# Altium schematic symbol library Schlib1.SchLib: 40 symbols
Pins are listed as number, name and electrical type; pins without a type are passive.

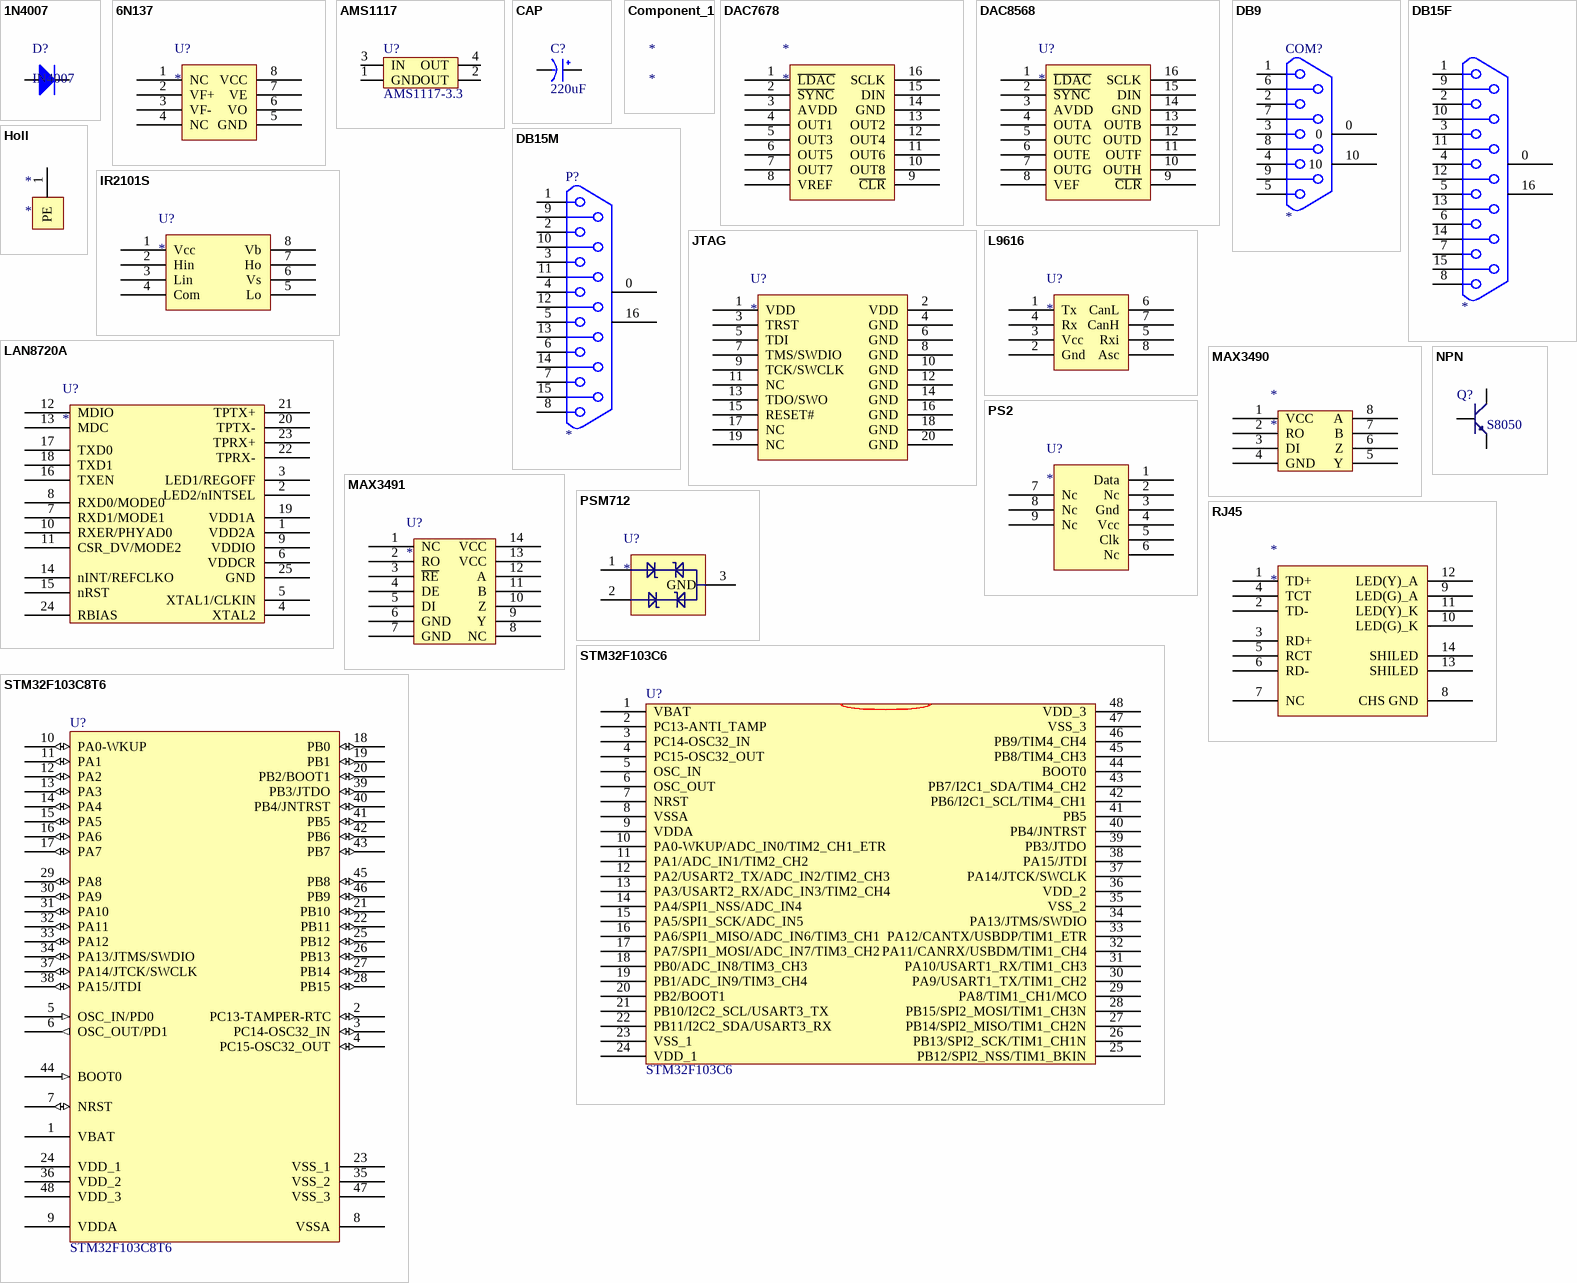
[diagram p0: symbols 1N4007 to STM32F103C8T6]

## 1N4007
designator D?, comment IN4007
footprint DIODE0.4
pins: 1 K, 2 A

## 6N137
designator U?
pins: 1 NC, 2 VF+, 3 VF-, 4 NC, 5 GND, 6 VO, 7 VE, 8 VCC

## AMS1117
designator U?, comment AMS1117-3.3
footprint AMS1117
footprint AMS1117
pins: 1 GND, 2 OUT, 3 IN, 4 OUT

## CAP
designator C?, comment 220uF
footprint C1206
footprint CAP2.54 (RB.1/.2)
footprint CAP5.08 (RB.2/.4)
footprint CAP7.62 (25V 2200uF)
footprint CAP10.16 (50V10000uF)
footprint CAP10.9 (50V 2200uF)
footprint CAP3.0 (100V 10uF)
footprint CAP8.0 (25V/4700uF)
footprint CAP8.0_2 (50V/4700uF)
footprint C7040 (7MM*4MM)
footprint CC1010 (SMD;W:10mm;L:10mm;)
footprint CC6.56.5
footprint CC88 (SMD;W:8mm;L:8mm;)
pins: 1 VCC, 2 GND

## Component_1
designator *

## DAC7678
designator *
pins: 1 ~{LDAC}, 2 ~{SYNC}, 3 AVDD, 4 OUT1, 5 OUT3, 6 OUT5, 7 OUT7, 8 VREF, 9 ~{CLR}, 10 OUT8, 11 OUT6, 12 OUT4, 13 OUT2, 14 GND, 15 DIN, 16 SCLK

## DAC8568
designator U?
pins: 1 ~{LDAC}, 2 ~{SYNC}, 3 AVDD, 4 OUTA, 5 OUTC, 6 OUTE, 7 OUTG, 8 VEF, 9 ~{CLR}, 10 OUTH, 11 OUTF, 12 OUTD, 13 OUTB, 14 GND, 15 DIN, 16 SCLK

## DB9
designator COM?
footprint DB9
footprint DB9-180
footprint DB9-180
pins: 0, 1, 2, 3, 4, 5, 6, 7, 8, 9, 10
2 alternate drawings of the same symbol

## DB15F
designator ?
footprint DB15F
pins: 0, 1, 2, 3, 4, 5, 6, 7, 8, 9, 10, 11, 12, 13, 14, 15, 16
2 alternate drawings of the same symbol

## DB15M
designator P?
footprint DB15M
footprint DB15M
footprint DB15M
pins: 0, 1, 2, 3, 4, 5, 6, 7, 8, 9, 10, 11, 12, 13, 14, 15, 16

## Holl
designator *
pins: 1 PE

## IR2101S
designator U?
footprint SO-8
pins: 1 Vcc, 2 Hin, 3 Lin, 4 Com, 5 Lo, 6 Vs, 7 Ho, 8 Vb

## JTAG
designator U?
pins: 1 VDD, 2 VDD, 3 TRST, 4 GND, 5 TDI, 6 GND, 7 TMS/SWDIO, 8 GND, 9 TCK/SWCLK, 10 GND, 11 NC, 12 GND, 13 TDO/SWO, 14 GND, 15 RESET#, 16 GND, 17 NC, 18 GND, 19 NC, 20 GND

## L9616
designator U?
footprint SOIC8
pins: 1 Tx, 2 Gnd, 3 Vcc, 4 Rx, 5 Rxi, 6 CanL, 7 CanH, 8 Asc

## LAN8720A
designator U?
pins: 1 VDD2A, 2 LED2/nINTSEL, 3 LED1/REGOFF, 4 XTAL2, 5 XTAL1/CLKIN, 6 VDDCR, 7 RXD1/MODE1, 8 RXD0/MODE0, 9 VDDIO, 10 RXER/PHYAD0, 11 CSR_DV/MODE2, 12 MDIO, 13 MDC, 14 nINT/REFCLKO, 15 nRST, 16 TXEN, 17 TXD0, 18 TXD1, 19 VDD1A, 20 TPTX-, 21 TPTX+, 22 TPRX-, 23 TPRX+, 24 RBIAS, 25 GND

## MAX3490
designator *
footprint SOP-4
footprint SO-8
pins: 1 VCC, 2 RO, 3 DI, 4 GND, 5 Y, 6 Z, 7 B, 8 A

## MAX3491
designator U?
footprint MAX3491 (TSOP, 14-Leads, Body 8.65x3.90mm, Pitch 1.27mm, IPC Medium Density)
pins: 1 NC, 2 RO, 3 ~{RE}, 4 DE, 5 DI, 6 GND, 7 GND, 8 NC, 9 Y, 10 Z, 11 B, 12 A, 13 VCC, 14 VCC

## NPN
designator Q?, comment S8050
8050/BCW846/BCW847
footprint SOT-23R
footprint NPN
pins: 1 E, 2 B, 3 C

## PS2
designator U?
footprint PS2
pins: 1 Data, 2 Nc, 3 Gnd, 4 Vcc, 5 Clk, 6 Nc, 7 Nc, 8 Nc, 9 Nc

## PSM712
designator U?
footprint SOT23-3 (SOT23, 3-Leads, Body 2.90x2.45mm, Pitch 0.95mm, IPC Medium Density)
pins: 1, 2, 3 GND

## RJ45
designator *
pins: 1 TD+, 2 TD-, 3 RD+, 4 TCT, 5 RCT, 6 RD-, 7 NC, 8 CHS GND, 9 LED(G)_A, 10 LED(G)_K, 11 LED(Y)_K, 12 LED(Y)_A, 13 SHILED, 14 SHILED

## STM32F103C6
designator U?
footprint LQFP48S (DPIN-0.5)
pins: 1 VBAT, 2 PC13-ANTI_TAMP, 3 PC14-OSC32_IN, 4 PC15-OSC32_OUT, 5 OSC_IN, 6 OSC_OUT, 7 NRST, 8 VSSA, 9 VDDA, 10 PA0-WKUP/ADC_IN0/TIM2_CH1_ETR, 11 PA1/ADC_IN1/TIM2_CH2, 12 PA2/USART2_TX/ADC_IN2/TIM2_CH3, 13 PA3/USART2_RX/ADC_IN3/TIM2_CH4, 14 PA4/SPI1_NSS/ADC_IN4, 15 PA5/SPI1_SCK/ADC_IN5, 16 PA6/SPI1_MISO/ADC_IN6/TIM3_CH1, 17 PA7/SPI1_MOSI/ADC_IN7/TIM3_CH2, 18 PB0/ADC_IN8/TIM3_CH3, 19 PB1/ADC_IN9/TIM3_CH4, 20 PB2/BOOT1, 21 PB10/I2C2_SCL/USART3_TX, 22 PB11/I2C2_SDA/USART3_RX, 23 VSS_1, 24 VDD_1, 25 PB12/SPI2_NSS/TIM1_BKIN, 26 PB13/SPI2_SCK/TIM1_CH1N, 27 PB14/SPI2_MISO/TIM1_CH2N, 28 PB15/SPI2_MOSI/TIM1_CH3N, 29 PA8/TIM1_CH1/MCO, 30 PA9/USART1_TX/TIM1_CH2, 31 PA10/USART1_RX/TIM1_CH3, 32 PA11/CANRX/USBDM/TIM1_CH4, 33 PA12/CANTX/USBDP/TIM1_ETR, 34 PA13/JTMS/SWDIO, 35 VSS_2, 36 VDD_2, 37 PA14/JTCK/SWCLK, 38 PA15/JTDI, 39 PB3/JTDO, 40 PB4/JNTRST, 41 PB5, 42 PB6/I2C1_SCL/TIM4_CH1, 43 PB7/I2C1_SDA/TIM4_CH2, 44 BOOT0, 45 PB8/TIM4_CH3, 46 PB9/TIM4_CH4, 47 VSS_3, 48 VDD_3
2 alternate drawings of the same symbol

## STM32F103C8T6
designator U?
footprint LQFP-48
pins: 1 VBAT (power), 2 PC13-TAMPER-RTC (io), 3 PC14-OSC32_IN (io), 4 PC15-OSC32_OUT (io), 5 OSC_IN/PD0 (in), 6 OSC_OUT/PD1 (out), 7 NRST (io), 8 VSSA (power), 9 VDDA (power), 10 PA0-WKUP (io), 11 PA1 (io), 12 PA2 (io), 13 PA3 (io), 14 PA4 (io), 15 PA5 (io), 16 PA6 (io), 17 PA7 (io), 18 PB0 (io), 19 PB1 (io), 20 PB2/BOOT1 (io), 21 PB10 (io), 22 PB11 (io), 23 VSS_1 (power), 24 VDD_1 (power), 25 PB12 (io), 26 PB13 (io), 27 PB14 (io), 28 PB15 (io), 29 PA8 (io), 30 PA9 (io), 31 PA10 (io), 32 PA11 (io), 33 PA12 (io), 34 PA13/JTMS/SWDIO (io), 35 VSS_2 (power), 36 VDD_2 (power), 37 PA14/JTCK/SWCLK (io), 38 PA15/JTDI (io), 39 PB3/JTDO (io), 40 PB4/JNTRST (io), 41 PB5 (io), 42 PB6 (io), 43 PB7 (io), 44 BOOT0 (in), 45 PB8 (io), 46 PB9 (io), 47 VSS_3 (power), 48 VDD_3 (power)

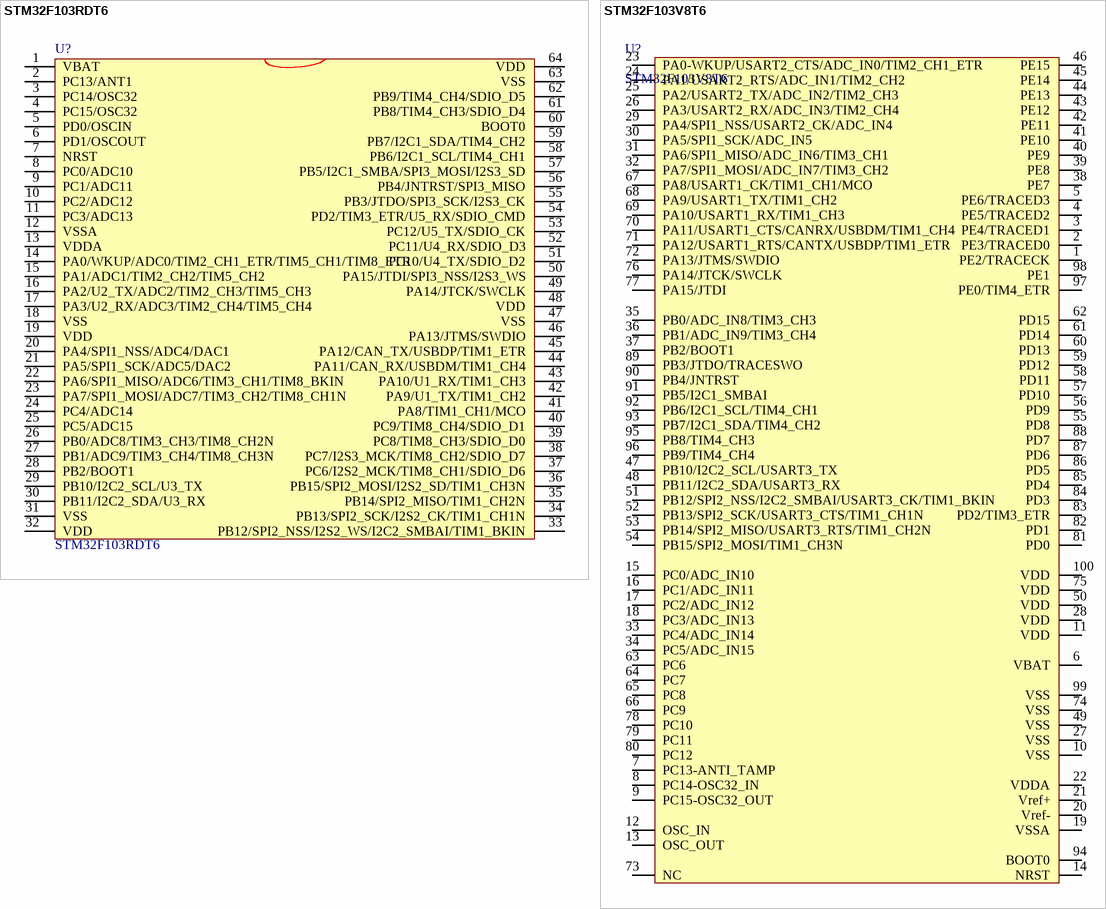
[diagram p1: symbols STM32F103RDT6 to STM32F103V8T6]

## STM32F103RDT6
designator U?
footprint LQFP64
footprint VRCNC_LQFP64
pins: 1 VBAT, 2 PC13/ANT1, 3 PC14/OSC32, 4 PC15/OSC32, 5 PD0/OSCIN, 6 PD1/OSCOUT, 7 NRST, 8 PC0/ADC10, 9 PC1/ADC11, 10 PC2/ADC12, 11 PC3/ADC13, 12 VSSA, 13 VDDA, 14 PA0/WKUP/ADC0/TIM2_CH1_ETR/TIM5_CH1/TIM8_ETR, 15 PA1/ADC1/TIM2_CH2/TIM5_CH2, 16 PA2/U2_TX/ADC2/TIM2_CH3/TIM5_CH3, 17 PA3/U2_RX/ADC3/TIM2_CH4/TIM5_CH4, 18 VSS, 19 VDD, 20 PA4/SPI1_NSS/ADC4/DAC1, 21 PA5/SPI1_SCK/ADC5/DAC2, 22 PA6/SPI1_MISO/ADC6/TIM3_CH1/TIM8_BKIN, 23 PA7/SPI1_MOSI/ADC7/TIM3_CH2/TIM8_CH1N, 24 PC4/ADC14, 25 PC5/ADC15, 26 PB0/ADC8/TIM3_CH3/TIM8_CH2N, 27 PB1/ADC9/TIM3_CH4/TIM8_CH3N, 28 PB2/BOOT1, 29 PB10/I2C2_SCL/U3_TX, 30 PB11/I2C2_SDA/U3_RX, 31 VSS, 32 VDD, 33 PB12/SPI2_NSS/I2S2_WS/I2C2_SMBAI/TIM1_BKIN, 34 PB13/SPI2_SCK/I2S2_CK/TIM1_CH1N, 35 PB14/SPI2_MISO/TIM1_CH2N, 36 PB15/SPI2_MOSI/I2S2_SD/TIM1_CH3N, 37 PC6/I2S2_MCK/TIM8_CH1/SDIO_D6, 38 PC7/I2S3_MCK/TIM8_CH2/SDIO_D7, 39 PC8/TIM8_CH3/SDIO_D0, 40 PC9/TIM8_CH4/SDIO_D1, 41 PA8/TIM1_CH1/MCO, 42 PA9/U1_TX/TIM1_CH2, 43 PA10/U1_RX/TIM1_CH3, 44 PA11/CAN_RX/USBDM/TIM1_CH4, 45 PA12/CAN_TX/USBDP/TIM1_ETR, 46 PA13/JTMS/SWDIO, 47 VSS, 48 VDD, 49 PA14/JTCK/SWCLK, 50 PA15/JTDI/SPI3_NSS/I2S3_WS, 51 PC10/U4_TX/SDIO_D2, 52 PC11/U4_RX/SDIO_D3, 53 PC12/U5_TX/SDIO_CK, 54 PD2/TIM3_ETR/U5_RX/SDIO_CMD, 55 PB3/JTDO/SPI3_SCK/I2S3_CK, 56 PB4/JNTRST/SPI3_MISO, 57 PB5/I2C1_SMBA/SPI3_MOSI/I2S3_SD, 58 PB6/I2C1_SCL/TIM4_CH1, 59 PB7/I2C1_SDA/TIM4_CH2, 60 BOOT0, 61 PB8/TIM4_CH3/SDIO_D4, 62 PB9/TIM4_CH4/SDIO_D5, 63 VSS, 64 VDD

## STM32F103V8T6
designator U?
footprint LQFP100 (TSQFP, 100-Leads, Body 16.0x16.0mm (max), Pitch 0.50mm, IPC Medium Density)
pins: 1 PE2/TRACECK, 2 PE3/TRACED0, 3 PE4/TRACED1, 4 PE5/TRACED2, 5 PE6/TRACED3, 6 VBAT, 7 PC13-ANTI_TAMP, 8 PC14-OSC32_IN, 9 PC15-OSC32_OUT, 10 VSS, 11 VDD, 12 OSC_IN, 13 OSC_OUT, 14 NRST, 15 PC0/ADC_IN10, 16 PC1/ADC_IN11, 17 PC2/ADC_IN12, 18 PC3/ADC_IN13, 19 VSSA, 20 Vref-, 21 Vref+, 22 VDDA, 23 PA0-WKUP/USART2_CTS/ADC_IN0/TIM2_CH1_ETR, 24 PA1/USART2_RTS/ADC_IN1/TIM2_CH2, 25 PA2/USART2_TX/ADC_IN2/TIM2_CH3, 26 PA3/USART2_RX/ADC_IN3/TIM2_CH4, 27 VSS, 28 VDD, 29 PA4/SPI1_NSS/USART2_CK/ADC_IN4, 30 PA5/SPI1_SCK/ADC_IN5, 31 PA6/SPI1_MISO/ADC_IN6/TIM3_CH1, 32 PA7/SPI1_MOSI/ADC_IN7/TIM3_CH2, 33 PC4/ADC_IN14, 34 PC5/ADC_IN15, 35 PB0/ADC_IN8/TIM3_CH3, 36 PB1/ADC_IN9/TIM3_CH4, 37 PB2/BOOT1, 38 PE7, 39 PE8, 40 PE9, 41 PE10, 42 PE11, 43 PE12, 44 PE13, 45 PE14, 46 PE15, 47 PB10/I2C2_SCL/USART3_TX, 48 PB11/I2C2_SDA/USART3_RX, 49 VSS, 50 VDD, 51 PB12/SPI2_NSS/I2C2_SMBAI/USART3_CK/TIM1_BKIN, 52 PB13/SPI2_SCK/USART3_CTS/TIM1_CH1N, 53 PB14/SPI2_MISO/USART3_RTS/TIM1_CH2N, 54 PB15/SPI2_MOSI/TIM1_CH3N, 55 PD8, 56 PD9, 57 PD10, 58 PD11, 59 PD12, 60 PD13, 61 PD14, 62 PD15, 63 PC6, 64 PC7, 65 PC8, 66 PC9, 67 PA8/USART1_CK/TIM1_CH1/MCO, 68 PA9/USART1_TX/TIM1_CH2, 69 PA10/USART1_RX/TIM1_CH3, 70 PA11/USART1_CTS/CANRX/USBDM/TIM1_CH4, 71 PA12/USART1_RTS/CANTX/USBDP/TIM1_ETR, 72 PA13/JTMS/SWDIO, 73 NC, 74 VSS, 75 VDD, 76 PA14/JTCK/SWCLK, 77 PA15/JTDI, 78 PC10, 79 PC11, 80 PC12, 81 PD0, 82 PD1, 83 PD2/TIM3_ETR, 84 PD3, 85 PD4, 86 PD5, 87 PD6, 88 PD7, 89 PB3/JTDO/TRACESWO, 90 PB4/JNTRST, 91 PB5/I2C1_SMBAI, 92 PB6/I2C1_SCL/TIM4_CH1, 93 PB7/I2C1_SDA/TIM4_CH2, 94 BOOT0, 95 PB8/TIM4_CH3, 96 PB9/TIM4_CH4, 97 PE0/TIM4_ETR, 98 PE1, 99 VSS, 100 VDD

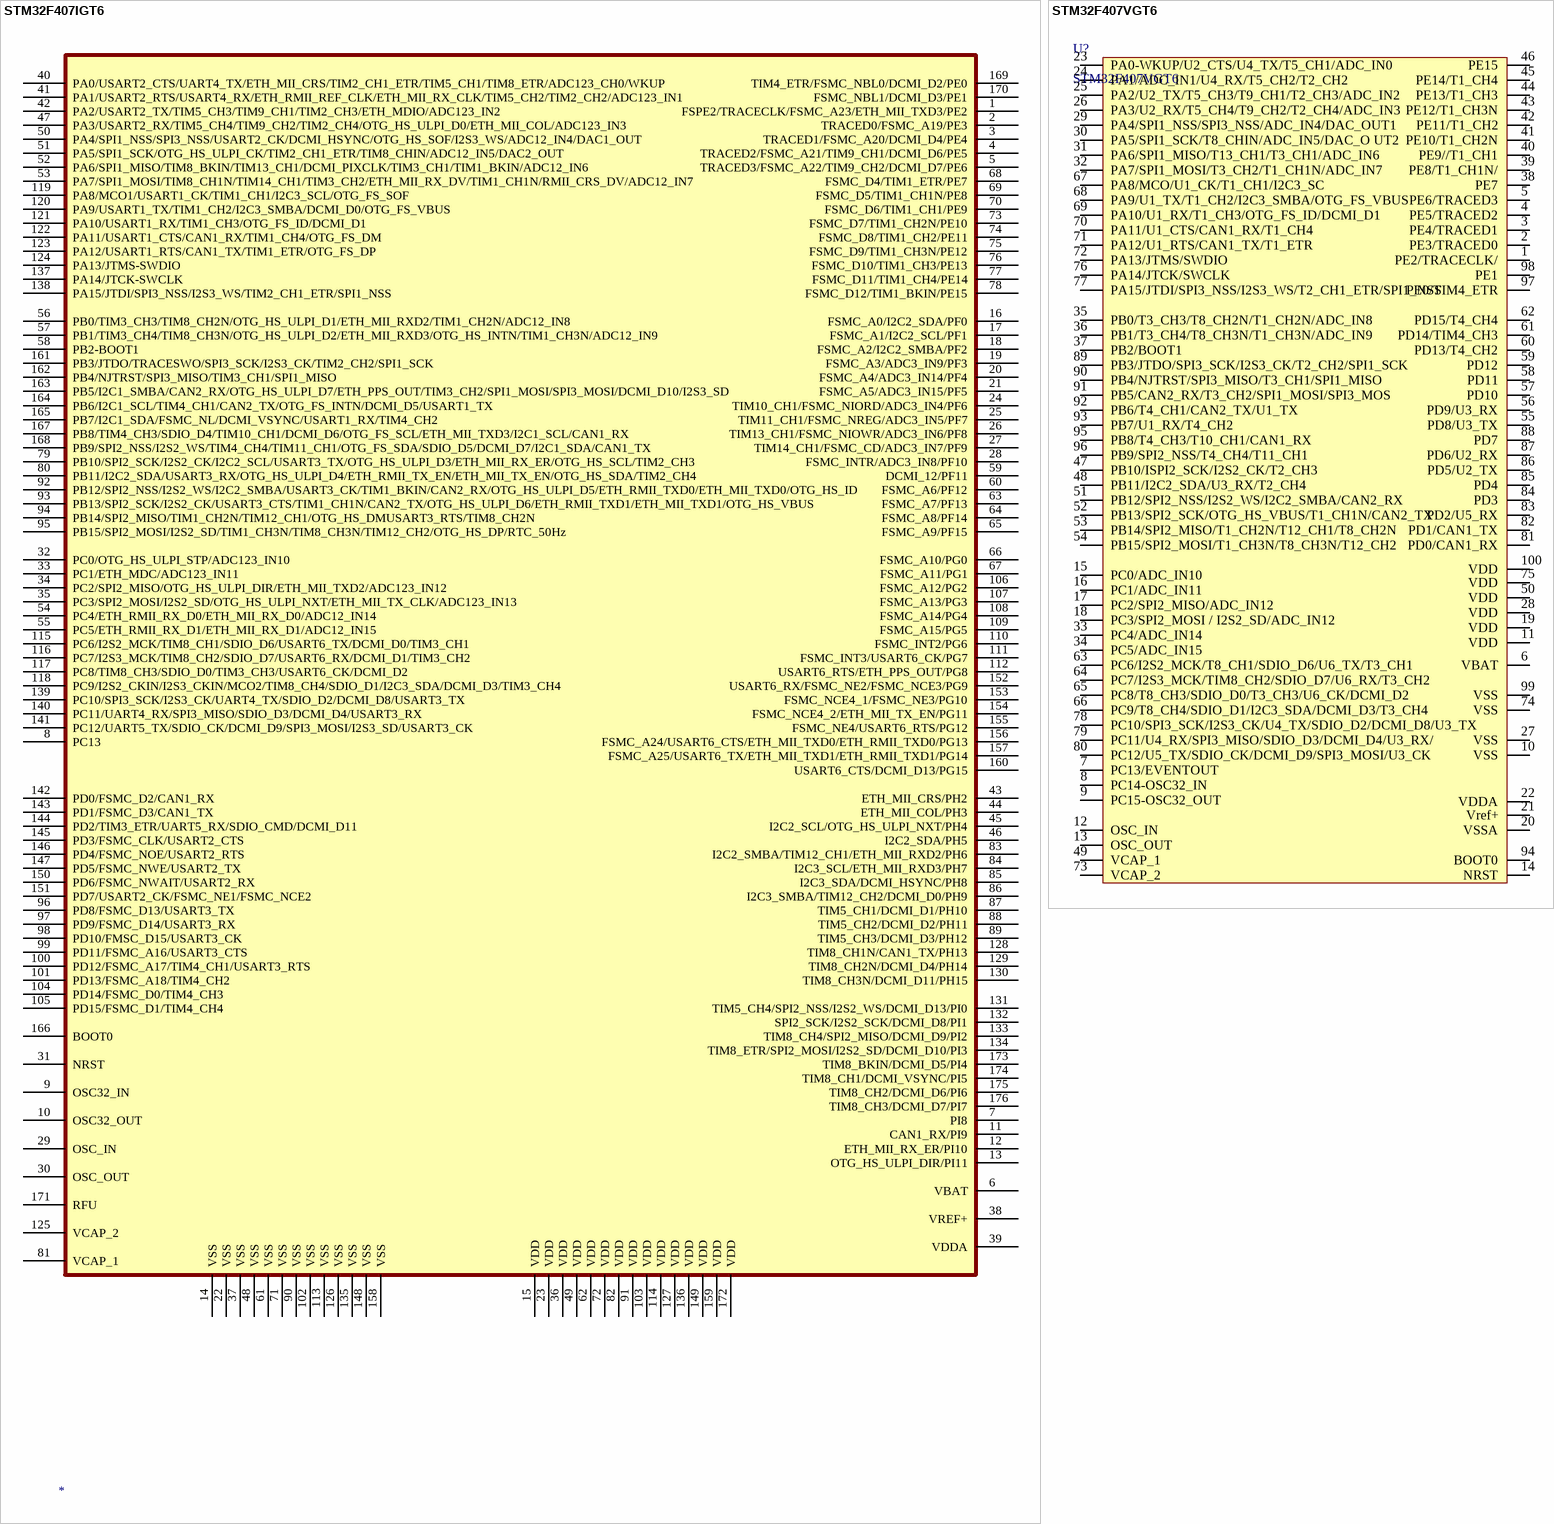
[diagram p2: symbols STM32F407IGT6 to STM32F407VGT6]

## STM32F407IGT6
designator ?
pins: 1 FSPE2/TRACECLK/FSMC_A23/ETH_MII_TXD3/PE2, 2 TRACED0/FSMC_A19/PE3, 3 TRACED1/FSMC_A20/DCMI_D4/PE4, 4 TRACED2/FSMC_A21/TIM9_CH1/DCMI_D6/PE5, 5 TRACED3/FSMC_A22/TIM9_CH2/DCMI_D7/PE6, 6 VBAT, 7 PI8, 8 PC13, 9 OSC32_IN, 10 OSC32_OUT, 11 CAN1_RX/PI9, 12 ETH_MII_RX_ER/PI10, 13 OTG_HS_ULPI_DIR/PI11, 14 VSS, 15 VDD, 16 FSMC_A0/I2C2_SDA/PF0, 17 FSMC_A1/I2C2_SCL/PF1, 18 FSMC_A2/I2C2_SMBA/PF2, 19 FSMC_A3/ADC3_IN9/PF3, 20 FSMC_A4/ADC3_IN14/PF4, 21 FSMC_A5/ADC3_IN15/PF5, 22 VSS, 23 VDD, 24 TIM10_CH1/FSMC_NIORD/ADC3_IN4/PF6, 25 TIM11_CH1/FSMC_NREG/ADC3_IN5/PF7, 26 TIM13_CH1/FSMC_NIOWR/ADC3_IN6/PF8, 27 TIM14_CH1/FSMC_CD/ADC3_IN7/PF9, 28 FSMC_INTR/ADC3_IN8/PF10, 29 OSC_IN, 30 OSC_OUT, 31 NRST, 32 PC0/OTG_HS_ULPI_STP/ADC123_IN10, 33 PC1/ETH_MDC/ADC123_IN11, 34 PC2/SPI2_MISO/OTG_HS_ULPI_DIR/ETH_MII_TXD2/ADC123_IN12, 35 PC3/SPI2_MOSI/I2S2_SD/OTG_HS_ULPI_NXT/ETH_MII_TX_CLK/ADC123_IN13, 36 VDD, 37 VSS, 38 VREF+, 39 VDDA, 40 PA0/USART2_CTS/UART4_TX/ETH_MII_CRS/TIM2_CH1_ETR/TIM5_CH1/TIM8_ETR/ADC123_CH0/WKUP, 41 PA1/USART2_RTS/USART4_RX/ETH_RMII_REF_CLK/ETH_MII_RX_CLK/TIM5_CH2/TIM2_CH2/ADC123_IN1, 42 PA2/USART2_TX/TIM5_CH3/TIM9_CH1/TIM2_CH3/ETH_MDIO/ADC123_IN2, 43 ETH_MII_CRS/PH2, 44 ETH_MII_COL/PH3, 45 I2C2_SCL/OTG_HS_ULPI_NXT/PH4, 46 I2C2_SDA/PH5, 47 PA3/USART2_RX/TIM5_CH4/TIM9_CH2/TIM2_CH4/OTG_HS_ULPI_D0/ETH_MII_COL/ADC123_IN3, 48 VSS, 49 VDD, 50 PA4/SPI1_NSS/SPI3_NSS/USART2_CK/DCMI_HSYNC/OTG_HS_SOF/I2S3_WS/ADC12_IN4/DAC1_OUT, 51 PA5/SPI1_SCK/OTG_HS_ULPI_CK/TIM2_CH1_ETR/TIM8_CHIN/ADC12_IN5/DAC2_OUT, 52 PA6/SPI1_MISO/TIM8_BKIN/TIM13_CH1/DCMI_PIXCLK/TIM3_CH1/TIM1_BKIN/ADC12_IN6, 53 PA7/SPI1_MOSI/TIM8_CH1N/TIM14_CH1/TIM3_CH2/ETH_MII_RX_DV/TIM1_CH1N/RMII_CRS_DV/ADC12_IN7, 54 PC4/ETH_RMII_RX_D0/ETH_MII_RX_D0/ADC12_IN14, 55 PC5/ETH_RMII_RX_D1/ETH_MII_RX_D1/ADC12_IN15, 56 PB0/TIM3_CH3/TIM8_CH2N/OTG_HS_ULPI_D1/ETH_MII_RXD2/TIM1_CH2N/ADC12_IN8, 57 PB1/TIM3_CH4/TIM8_CH3N/OTG_HS_ULPI_D2/ETH_MII_RXD3/OTG_HS_INTN/TIM1_CH3N/ADC12_IN9, 58 PB2-BOOT1, 59 DCMI_12/PF11, 60 FSMC_A6/PF12, 61 VSS, 62 VDD, 63 FSMC_A7/PF13, 64 FSMC_A8/PF14, 65 FSMC_A9/PF15, 66 FSMC_A10/PG0, 67 FSMC_A11/PG1, 68 FSMC_D4/TIM1_ETR/PE7, 69 FSMC_D5/TIM1_CH1N/PE8, 70 FSMC_D6/TIM1_CH1/PE9, 71 VSS, 72 VDD, 73 FSMC_D7/TIM1_CH2N/PE10, 74 FSMC_D8/TIM1_CH2/PE11, 75 FSMC_D9/TIM1_CH3N/PE12, 76 FSMC_D10/TIM1_CH3/PE13, 77 FSMC_D11/TIM1_CH4/PE14, 78 FSMC_D12/TIM1_BKIN/PE15, 79 PB10/SPI2_SCK/I2S2_CK/I2C2_SCL/USART3_TX/OTG_HS_ULPI_D3/ETH_MII_RX_ER/OTG_HS_SCL/TIM2_CH3, 80 PB11/I2C2_SDA/USART3_RX/OTG_HS_ULPI_D4/ETH_RMII_TX_EN/ETH_MII_TX_EN/OTG_HS_SDA/TIM2_CH4, 81 VCAP_1, 82 VDD, 83 I2C2_SMBA/TIM12_CH1/ETH_MII_RXD2/PH6, 84 I2C3_SCL/ETH_MII_RXD3/PH7, 85 I2C3_SDA/DCMI_HSYNC/PH8, 86 I2C3_SMBA/TIM12_CH2/DCMI_D0/PH9, 87 TIM5_CH1/DCMI_D1/PH10, 88 TIM5_CH2/DCMI_D2/PH11, 89 TIM5_CH3/DCMI_D3/PH12, 90 VSS, 91 VDD, 92 PB12/SPI2_NSS/I2S2_WS/I2C2_SMBA/USART3_CK/TIM1_BKIN/CAN2_RX/OTG_HS_ULPI_D5/ETH_RMII_TXD0/ETH_MII_TXD0/OTG_HS_ID, 93 PB13/SPI2_SCK/I2S2_CK/USART3_CTS/TIM1_CH1N/CAN2_TX/OTG_HS_ULPI_D6/ETH_RMII_TXD1/ETH_MII_TXD1/OTG_HS_VBUS, 94 PB14/SPI2_MISO/TIM1_CH2N/TIM12_CH1/OTG_HS_DMUSART3_RTS/TIM8_CH2N, 95 PB15/SPI2_MOSI/I2S2_SD/TIM1_CH3N/TIM8_CH3N/TIM12_CH2/OTG_HS_DP/RTC_50Hz, 96 PD8/FSMC_D13/USART3_TX, 97 PD9/FSMC_D14/USART3_RX, 98 PD10/FMSC_D15/USART3_CK, 99 PD11/FSMC_A16/USART3_CTS, 100 PD12/FSMC_A17/TIM4_CH1/USART3_RTS, 101 PD13/FSMC_A18/TIM4_CH2, 102 VSS, 103 VDD, 104 PD14/FSMC_D0/TIM4_CH3, 105 PD15/FSMC_D1/TIM4_CH4, 106 FSMC_A12/PG2, 107 FSMC_A13/PG3, 108 FSMC_A14/PG4, 109 FSMC_A15/PG5, 110 FSMC_INT2/PG6, 111 FSMC_INT3/USART6_CK/PG7, 112 USART6_RTS/ETH_PPS_OUT/PG8, 113 VSS, 114 VDD, 115 PC6/I2S2_MCK/TIM8_CH1/SDIO_D6/USART6_TX/DCMI_D0/TIM3_CH1, 116 PC7/I2S3_MCK/TIM8_CH2/SDIO_D7/USART6_RX/DCMI_D1/TIM3_CH2, 117 PC8/TIM8_CH3/SDIO_D0/TIM3_CH3/USART6_CK/DCMI_D2, 118 PC9/I2S2_CKIN/I2S3_CKIN/MCO2/TIM8_CH4/SDIO_D1/I2C3_SDA/DCMI_D3/TIM3_CH4, 119 PA8/MCO1/USART1_CK/TIM1_CH1/I2C3_SCL/OTG_FS_SOF, 120 PA9/USART1_TX/TIM1_CH2/I2C3_SMBA/DCMI_D0/OTG_FS_VBUS, 121 PA10/USART1_RX/TIM1_CH3/OTG_FS_ID/DCMI_D1, 122 PA11/USART1_CTS/CAN1_RX/TIM1_CH4/OTG_FS_DM, 123 PA12/USART1_RTS/CAN1_TX/TIM1_ETR/OTG_FS_DP, 124 PA13/JTMS-SWDIO, 125 VCAP_2, 126 VSS, 127 VDD, 128 TIM8_CH1N/CAN1_TX/PH13, 129 TIM8_CH2N/DCMI_D4/PH14, 130 TIM8_CH3N/DCMI_D11/PH15, 131 TIM5_CH4/SPI2_NSS/I2S2_WS/DCMI_D13/PI0, 132 SPI2_SCK/I2S2_SCK/DCMI_D8/PI1, 133 TIM8_CH4/SPI2_MISO/DCMI_D9/PI2, 134 TIM8_ETR/SPI2_MOSI/I2S2_SD/DCMI_D10/PI3, 135 VSS, 136 VDD, 137 PA14/JTCK-SWCLK, 138 PA15/JTDI/SPI3_NSS/I2S3_WS/TIM2_CH1_ETR/SPI1_NSS, 139 PC10/SPI3_SCK/I2S3_CK/UART4_TX/SDIO_D2/DCMI_D8/USART3_TX, 140 PC11/UART4_RX/SPI3_MISO/SDIO_D3/DCMI_D4/USART3_RX, 141 PC12/UART5_TX/SDIO_CK/DCMI_D9/SPI3_MOSI/I2S3_SD/USART3_CK, 142 PD0/FSMC_D2/CAN1_RX, 143 PD1/FSMC_D3/CAN1_TX, 144 PD2/TIM3_ETR/UART5_RX/SDIO_CMD/DCMI_D11, 145 PD3/FSMC_CLK/USART2_CTS, 146 PD4/FSMC_NOE/USART2_RTS, 147 PD5/FSMC_NWE/USART2_TX, 148 VSS, 149 VDD, 150 PD6/FSMC_NWAIT/USART2_RX, 151 PD7/USART2_CK/FSMC_NE1/FSMC_NCE2, 152 USART6_RX/FSMC_NE2/FSMC_NCE3/PG9, 153 FSMC_NCE4_1/FSMC_NE3/PG10, 154 FSMC_NCE4_2/ETH_MII_TX_EN/PG11, 155 FSMC_NE4/USART6_RTS/PG12, 156 FSMC_A24/USART6_CTS/ETH_MII_TXD0/ETH_RMII_TXD0/PG13, 157 FSMC_A25/USART6_TX/ETH_MII_TXD1/ETH_RMII_TXD1/PG14, 158 VSS, 159 VDD, 160 USART6_CTS/DCMI_D13/PG15, 161 PB3/JTDO/TRACESWO/SPI3_SCK/I2S3_CK/TIM2_CH2/SPI1_SCK, 162 PB4/NJTRST/SPI3_MISO/TIM3_CH1/SPI1_MISO, 163 PB5/I2C1_SMBA/CAN2_RX/OTG_HS_ULPI_D7/ETH_PPS_OUT/TIM3_CH2/SPI1_MOSI/SPI3_MOSI/DCMI_D10/I2S3_SD, 164 PB6/I2C1_SCL/TIM4_CH1/CAN2_TX/OTG_FS_INTN/DCMI_D5/USART1_TX, 165 PB7/I2C1_SDA/FSMC_NL/DCMI_VSYNC/USART1_RX/TIM4_CH2, 166 BOOT0, 167 PB8/TIM4_CH3/SDIO_D4/TIM10_CH1/DCMI_D6/OTG_FS_SCL/ETH_MII_TXD3/I2C1_SCL/CAN1_RX, 168 PB9/SPI2_NSS/I2S2_WS/TIM4_CH4/TIM11_CH1/OTG_FS_SDA/SDIO_D5/DCMI_D7/I2C1_SDA/CAN1_TX, 169 TIM4_ETR/FSMC_NBL0/DCMI_D2/PE0, 170 FSMC_NBL1/DCMI_D3/PE1, 171 RFU, 172 VDD, 173 TIM8_BKIN/DCMI_D5/PI4, 174 TIM8_CH1/DCMI_VSYNC/PI5, 175 TIM8_CH2/DCMI_D6/PI6, 176 TIM8_CH3/DCMI_D7/PI7

## STM32F407VGT6
designator U?
footprint LQFP100 (TSQFP, 100-Leads, Body 16.0x16.0mm (max), Pitch 0.50mm, IPC Medium Density)
pins: 1 PE2/TRACECLK/, 2 PE3/TRACED0, 3 PE4/TRACED1, 4 PE5/TRACED2, 5 PE6/TRACED3, 6 VBAT, 7 PC13/EVENTOUT, 8 PC14-OSC32_IN, 9 PC15-OSC32_OUT, 10 VSS, 11 VDD, 12 OSC_IN, 13 OSC_OUT, 14 NRST, 15 PC0/ADC_IN10, 16 PC1/ADC_IN11, 17 PC2/SPI2_MISO/ADC_IN12, 18 PC3/SPI2_MOSI / I2S2_SD/ADC_IN12 , 19 VDD, 20 VSSA, 21 Vref+, 22 VDDA, 23 PA0-WKUP/U2_CTS/U4_TX/T5_CH1/ADC_IN0, 24 PA1/ADC_IN1/U4_RX/T5_CH2/T2_CH2, 25 PA2/U2_TX/T5_CH3/T9_CH1/T2_CH3/ADC_IN2, 26 PA3/U2_RX/T5_CH4/T9_CH2/T2_CH4/ADC_IN3, 27 VSS, 28 VDD, 29 PA4/SPI1_NSS/SPI3_NSS/ADC_IN4/DAC_OUT1, 30 PA5/SPI1_SCK/T8_CHIN/ADC_IN5/DAC_O UT2, 31 PA6/SPI1_MISO/T13_CH1/T3_CH1/ADC_IN6, 32 PA7/SPI1_MOSI/T3_CH2/T1_CH1N/ADC_IN7, 33 PC4/ADC_IN14, 34 PC5/ADC_IN15, 35 PB0/T3_CH3/T8_CH2N/T1_CH2N/ADC_IN8, 36 PB1/T3_CH4/T8_CH3N/T1_CH3N/ADC_IN9, 37 PB2/BOOT1, 38 PE7, 39 PE8/T1_CH1N/, 40 PE9//T1_CH1, 41 PE10/T1_CH2N, 42 PE11/T1_CH2, 43 PE12/T1_CH3N, 44 PE13/T1_CH3, 45 PE14/T1_CH4, 46 PE15, 47 PB10/ISPI2_SCK/I2S2_CK/T2_CH3, 48 PB11/I2C2_SDA/U3_RX/T2_CH4, 49 VCAP_1, 50 VDD, 51 PB12/SPI2_NSS/I2S2_WS/I2C2_SMBA/CAN2_RX, 52 PB13/SPI2_SCK/OTG_HS_VBUS/T1_CH1N/CAN2_TX, 53 PB14/SPI2_MISO/T1_CH2N/T12_CH1/T8_CH2N, 54 PB15/SPI2_MOSI/T1_CH3N/T8_CH3N/T12_CH2, 55 PD8/U3_TX, 56 PD9/U3_RX, 57 PD10, 58 PD11, 59 PD12, 60 PD13/T4_CH2, 61 PD14/TIM4_CH3, 62 PD15/T4_CH4, 63 PC6/I2S2_MCK/T8_CH1/SDIO_D6/U6_TX/T3_CH1, 64 PC7/I2S3_MCK/TIM8_CH2/SDIO_D7/U6_RX/T3_CH2, 65 PC8/T8_CH3/SDIO_D0/T3_CH3/U6_CK/DCMI_D2, 66 PC9/T8_CH4/SDIO_D1/I2C3_SDA/DCMI_D3/T3_CH4, 67 PA8/MCO/U1_CK/T1_CH1/I2C3_SC, 68 PA9/U1_TX/T1_CH2/I2C3_SMBA/OTG_FS_VBUS, 69 PA10/U1_RX/T1_CH3/OTG_FS_ID/DCMI_D1, 70 PA11/U1_CTS/CAN1_RX/T1_CH4, 71 PA12/U1_RTS/CAN1_TX/T1_ETR, 72 PA13/JTMS/SWDIO, 73 VCAP_2, 74 VSS, 75 VDD, 76 PA14/JTCK/SWCLK, 77 PA15/JTDI/SPI3_NSS/I2S3_WS/T2_CH1_ETR/SPI1_NSS, 78 PC10/SPI3_SCK/I2S3_CK/U4_TX/SDIO_D2/DCMI_D8/U3_TX, 79 PC11/U4_RX/SPI3_MISO/SDIO_D3/DCMI_D4/U3_RX/, 80 PC12/U5_TX/SDIO_CK/DCMI_D9/SPI3_MOSI/U3_CK, 81 PD0/CAN1_RX, 82 PD1/CAN1_TX, 83 PD2/U5_RX, 84 PD3, 85 PD4, 86 PD5/U2_TX, 87 PD6/U2_RX, 88 PD7, 89 PB3/JTDO/SPI3_SCK/I2S3_CK/T2_CH2/SPI1_SCK, 90 PB4/NJTRST/SPI3_MISO/T3_CH1/SPI1_MISO, 91 PB5/CAN2_RX/T3_CH2/SPI1_MOSI/SPI3_MOS, 92 PB6/T4_CH1/CAN2_TX/U1_TX, 93 PB7/U1_RX/T4_CH2, 94 BOOT0, 95 PB8/T4_CH3/T10_CH1/CAN1_RX, 96 PB9/SPI2_NSS/T4_CH4/T11_CH1, 97 PE0/TIM4_ETR, 98 PE1, 99 VSS, 100 VDD

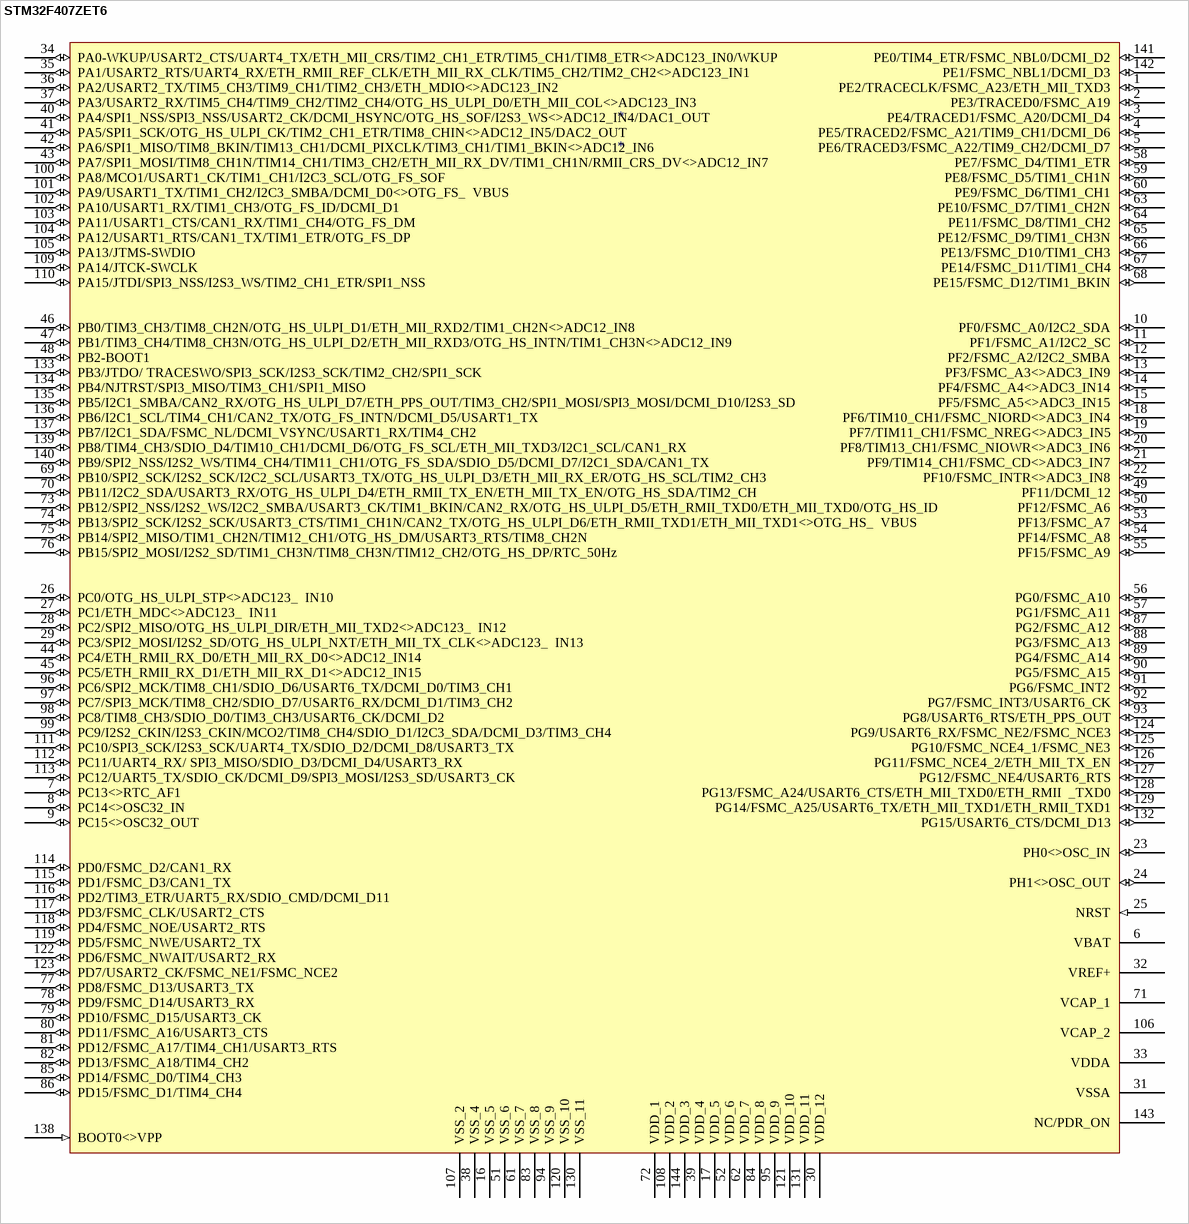
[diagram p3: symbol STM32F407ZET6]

## STM32F407ZET6
designator *
pins: 1 PE2/TRACECLK/FSMC_A23/ETH_MII_TXD3 (io), 2 PE3/TRACED0/FSMC_A19 (io), 3 PE4/TRACED1/FSMC_A20/DCMI_D4 (io), 4 PE5/TRACED2/FSMC_A21/TIM9_CH1/DCMI_D6 (io), 5 PE6/TRACED3/FSMC_A22/TIM9_CH2/DCMI_D7 (io), 6 VBAT (power), 7 PC13<>RTC_AF1 (io), 8 PC14<>OSC32_IN (io), 9 PC15<>OSC32_OUT (io), 10 PF0/FSMC_A0/I2C2_SDA (io), 11 PF1/FSMC_A1/I2C2_SC (io), 12 PF2/FSMC_A2/I2C2_SMBA (io), 13 PF3/FSMC_A3<>ADC3_IN9 (io), 14 PF4/FSMC_A4<>ADC3_IN14 (io), 15 PF5/FSMC_A5<>ADC3_IN15 (io), 16 VSS_5 (power), 17 VDD_5 (power), 18 PF6/TIM10_CH1/FSMC_NIORD<>ADC3_IN4 (io), 19 PF7/TIM11_CH1/FSMC_NREG<>ADC3_IN5 (io), 20 PF8/TIM13_CH1/FSMC_NIOWR<>ADC3_IN6 (io), 21 PF9/TIM14_CH1/FSMC_CD<>ADC3_IN7 (io), 22 PF10/FSMC_INTR<>ADC3_IN8 (io), 23 PH0<>OSC_IN (io), 24 PH1<>OSC_OUT (io), 25 NRST (in), 26 PC0/OTG_HS_ULPI_STP<>ADC123_  IN10 (io), 27 PC1/ETH_MDC<>ADC123_  IN11 (io), 28 PC2/SPI2_MISO/OTG_HS_ULPI_DIR/ETH_MII_TXD2<>ADC123_  IN12 (io), 29 PC3/SPI2_MOSI/I2S2_SD/OTG_HS_ULPI_NXT/ETH_MII_TX_CLK<>ADC123_  IN13 (io), 30 VDD_12 (power), 31 VSSA (power), 32 VREF+ (power), 33 VDDA (power), 34 PA0-WKUP/USART2_CTS/UART4_TX/ETH_MII_CRS/TIM2_CH1_ETR/TIM5_CH1/TIM8_ETR<>ADC123_IN0/WKUP (io), 35 PA1/USART2_RTS/UART4_RX/ETH_RMII_REF_CLK/ETH_MII_RX_CLK/TIM5_CH2/TIM2_CH2<>ADC123_IN1 (io), 36 PA2/USART2_TX/TIM5_CH3/TIM9_CH1/TIM2_CH3/ETH_MDIO<>ADC123_IN2 (io), 37 PA3/USART2_RX/TIM5_CH4/TIM9_CH2/TIM2_CH4/OTG_HS_ULPI_D0/ETH_MII_COL<>ADC123_IN3 (io), 38 VSS_4 (power), 39 VDD_4 (power), 40 PA4/SPI1_NSS/SPI3_NSS/USART2_CK/DCMI_HSYNC/OTG_HS_SOF/I2S3_WS<>ADC12_IN4/DAC1_OUT (io), 41 PA5/SPI1_SCK/OTG_HS_ULPI_CK/TIM2_CH1_ETR/TIM8_CHIN<>ADC12_IN5/DAC2_OUT (io), 42 PA6/SPI1_MISO/TIM8_BKIN/TIM13_CH1/DCMI_PIXCLK/TIM3_CH1/TIM1_BKIN<>ADC12_IN6 (io), 43 PA7/SPI1_MOSI/TIM8_CH1N/TIM14_CH1/TIM3_CH2/ETH_MII_RX_DV/TIM1_CH1N/RMII_CRS_DV<>ADC12_IN7 (io), 44 PC4/ETH_RMII_RX_D0/ETH_MII_RX_D0<>ADC12_IN14 (io), 45 PC5/ETH_RMII_RX_D1/ETH_MII_RX_D1<>ADC12_IN15 (io), 46 PB0/TIM3_CH3/TIM8_CH2N/OTG_HS_ULPI_D1/ETH_MII_RXD2/TIM1_CH2N<>ADC12_IN8 (io), 47 PB1/TIM3_CH4/TIM8_CH3N/OTG_HS_ULPI_D2/ETH_MII_RXD3/OTG_HS_INTN/TIM1_CH3N<>ADC12_IN9 (io), 48 PB2-BOOT1 (io), 49 PF11/DCMI_12 (io), 50 PF12/FSMC_A6 (io), 51 VSS_6 (power), 52 VDD_6 (power), 53 PF13/FSMC_A7 (io), 54 PF14/FSMC_A8 (io), 55 PF15/FSMC_A9 (io), 56 PG0/FSMC_A10 (io), 57 PG1/FSMC_A11 (io), 58 PE7/FSMC_D4/TIM1_ETR (io), 59 PE8/FSMC_D5/TIM1_CH1N (io), 60 PE9/FSMC_D6/TIM1_CH1 (io), 61 VSS_7 (power), 62 VDD_7 (power), 63 PE10/FSMC_D7/TIM1_CH2N (io), 64 PE11/FSMC_D8/TIM1_CH2 (io), 65 PE12/FSMC_D9/TIM1_CH3N (io), 66 PE13/FSMC_D10/TIM1_CH3 (io), 67 PE14/FSMC_D11/TIM1_CH4 (io), 68 PE15/FSMC_D12/TIM1_BKIN (io), 69 PB10/SPI2_SCK/I2S2_SCK/I2C2_SCL/USART3_TX/OTG_HS_ULPI_D3/ETH_MII_RX_ER/OTG_HS_SCL/TIM2_CH3 (io), 70 PB11/I2C2_SDA/USART3_RX/OTG_HS_ULPI_D4/ETH_RMII_TX_EN/ETH_MII_TX_EN/OTG_HS_SDA/TIM2_CH (io), 71 VCAP_1 (power), 72 VDD_1 (power), 73 PB12/SPI2_NSS/I2S2_WS/I2C2_SMBA/USART3_CK/TIM1_BKIN/CAN2_RX/OTG_HS_ULPI_D5/ETH_RMII_TXD0/ETH_MII_TXD0/OTG_HS_ID (io), 74 PB13/SPI2_SCK/I2S2_SCK/USART3_CTS/TIM1_CH1N/CAN2_TX/OTG_HS_ULPI_D6/ETH_RMII_TXD1/ETH_MII_TXD1<>OTG_HS_  VBUS (io), 75 PB14/SPI2_MISO/TIM1_CH2N/TIM12_CH1/OTG_HS_DM/USART3_RTS/TIM8_CH2N (io), 76 PB15/SPI2_MOSI/I2S2_SD/TIM1_CH3N/TIM8_CH3N/TIM12_CH2/OTG_HS_DP/RTC_50Hz (io), 77 PD8/FSMC_D13/USART3_TX (io), 78 PD9/FSMC_D14/USART3_RX (io), 79 PD10/FSMC_D15/USART3_CK (io), 80 PD11/FSMC_A16/USART3_CTS (io), 81 PD12/FSMC_A17/TIM4_CH1/USART3_RTS (io), 82 PD13/FSMC_A18/TIM4_CH2 (io), 83 VSS_8 (power), 84 VDD_8 (power), 85 PD14/FSMC_D0/TIM4_CH3 (io), 86 PD15/FSMC_D1/TIM4_CH4 (io), 87 PG2/FSMC_A12 (io), 88 PG3/FSMC_A13 (io), 89 PG4/FSMC_A14 (io), 90 PG5/FSMC_A15 (io), 91 PG6/FSMC_INT2 (io), 92 PG7/FSMC_INT3/USART6_CK (io), 93 PG8/USART6_RTS/ETH_PPS_OUT (io), 94 VSS_9 (power), 95 VDD_9 (power), 96 PC6/SPI2_MCK/TIM8_CH1/SDIO_D6/USART6_TX/DCMI_D0/TIM3_CH1 (io), 97 PC7/SPI3_MCK/TIM8_CH2/SDIO_D7/USART6_RX/DCMI_D1/TIM3_CH2 (io), 98 PC8/TIM8_CH3/SDIO_D0/TIM3_CH3/USART6_CK/DCMI_D2 (io), 99 PC9/I2S2_CKIN/I2S3_CKIN/MCO2/TIM8_CH4/SDIO_D1/I2C3_SDA/DCMI_D3/TIM3_CH4 (io), 100 PA8/MCO1/USART1_CK/TIM1_CH1/I2C3_SCL/OTG_FS_SOF (io), 101 PA9/USART1_TX/TIM1_CH2/I2C3_SMBA/DCMI_D0<>OTG_FS_  VBUS (io), 102 PA10/USART1_RX/TIM1_CH3/OTG_FS_ID/DCMI_D1 (io), 103 PA11/USART1_CTS/CAN1_RX/TIM1_CH4/OTG_FS_DM (io), 104 PA12/USART1_RTS/CAN1_TX/TIM1_ETR/OTG_FS_DP (io), 105 PA13/JTMS-SWDIO (io), 106 VCAP_2 (power), 107 VSS_2 (power), 108 VDD_2 (power), 109 PA14/JTCK-SWCLK (io), 110 PA15/JTDI/SPI3_NSS/I2S3_WS/TIM2_CH1_ETR/SPI1_NSS (io), 111 PC10/SPI3_SCK/I2S3_SCK/UART4_TX/SDIO_D2/DCMI_D8/USART3_TX (io), 112 PC11/UART4_RX/ SPI3_MISO/SDIO_D3/DCMI_D4/USART3_RX (io), 113 PC12/UART5_TX/SDIO_CK/DCMI_D9/SPI3_MOSI/I2S3_SD/USART3_CK (io), 114 PD0/FSMC_D2/CAN1_RX (io), 115 PD1/FSMC_D3/CAN1_TX (io), 116 PD2/TIM3_ETR/UART5_RX/SDIO_CMD/DCMI_D11 (io), 117 PD3/FSMC_CLK/USART2_CTS (io), 118 PD4/FSMC_NOE/USART2_RTS (io), 119 PD5/FSMC_NWE/USART2_TX (io), 120 VSS_10 (power), 121 VDD_10 (power), 122 PD6/FSMC_NWAIT/USART2_RX (io), 123 PD7/USART2_CK/FSMC_NE1/FSMC_NCE2 (io), 124 PG9/USART6_RX/FSMC_NE2/FSMC_NCE3 (io), 125 PG10/FSMC_NCE4_1/FSMC_NE3 (io), 126 PG11/FSMC_NCE4_2/ETH_MII_TX_EN (io), 127 PG12/FSMC_NE4/USART6_RTS (io), 128 PG13/FSMC_A24/USART6_CTS/ETH_MII_TXD0/ETH_RMII  _TXD0 (io), 129 PG14/FSMC_A25/USART6_TX/ETH_MII_TXD1/ETH_RMII_TXD1 (io), 130 VSS_11 (power), 131 VDD_11 (power), 132 PG15/USART6_CTS/DCMI_D13 (io), 133 PB3/JTDO/ TRACESWO/SPI3_SCK/I2S3_SCK/TIM2_CH2/SPI1_SCK (io), 134 PB4/NJTRST/SPI3_MISO/TIM3_CH1/SPI1_MISO (io), 135 PB5/I2C1_SMBA/CAN2_RX/OTG_HS_ULPI_D7/ETH_PPS_OUT/TIM3_CH2/SPI1_MOSI/SPI3_MOSI/DCMI_D10/I2S3_SD (io), 136 PB6/I2C1_SCL/TIM4_CH1/CAN2_TX/OTG_FS_INTN/DCMI_D5/USART1_TX (io), 137 PB7/I2C1_SDA/FSMC_NL/DCMI_VSYNC/USART1_RX/TIM4_CH2 (io), 138 BOOT0<>VPP (in), 139 PB8/TIM4_CH3/SDIO_D4/TIM10_CH1/DCMI_D6/OTG_FS_SCL/ETH_MII_TXD3/I2C1_SCL/CAN1_RX (io), 140 PB9/SPI2_NSS/I2S2_WS/TIM4_CH4/TIM11_CH1/OTG_FS_SDA/SDIO_D5/DCMI_D7/I2C1_SDA/CAN1_TX (io), 141 PE0/TIM4_ETR/FSMC_NBL0/DCMI_D2 (io), 142 PE1/FSMC_NBL1/DCMI_D3 (io), 143 NC/PDR_ON (power), 144 VDD_3 (power)

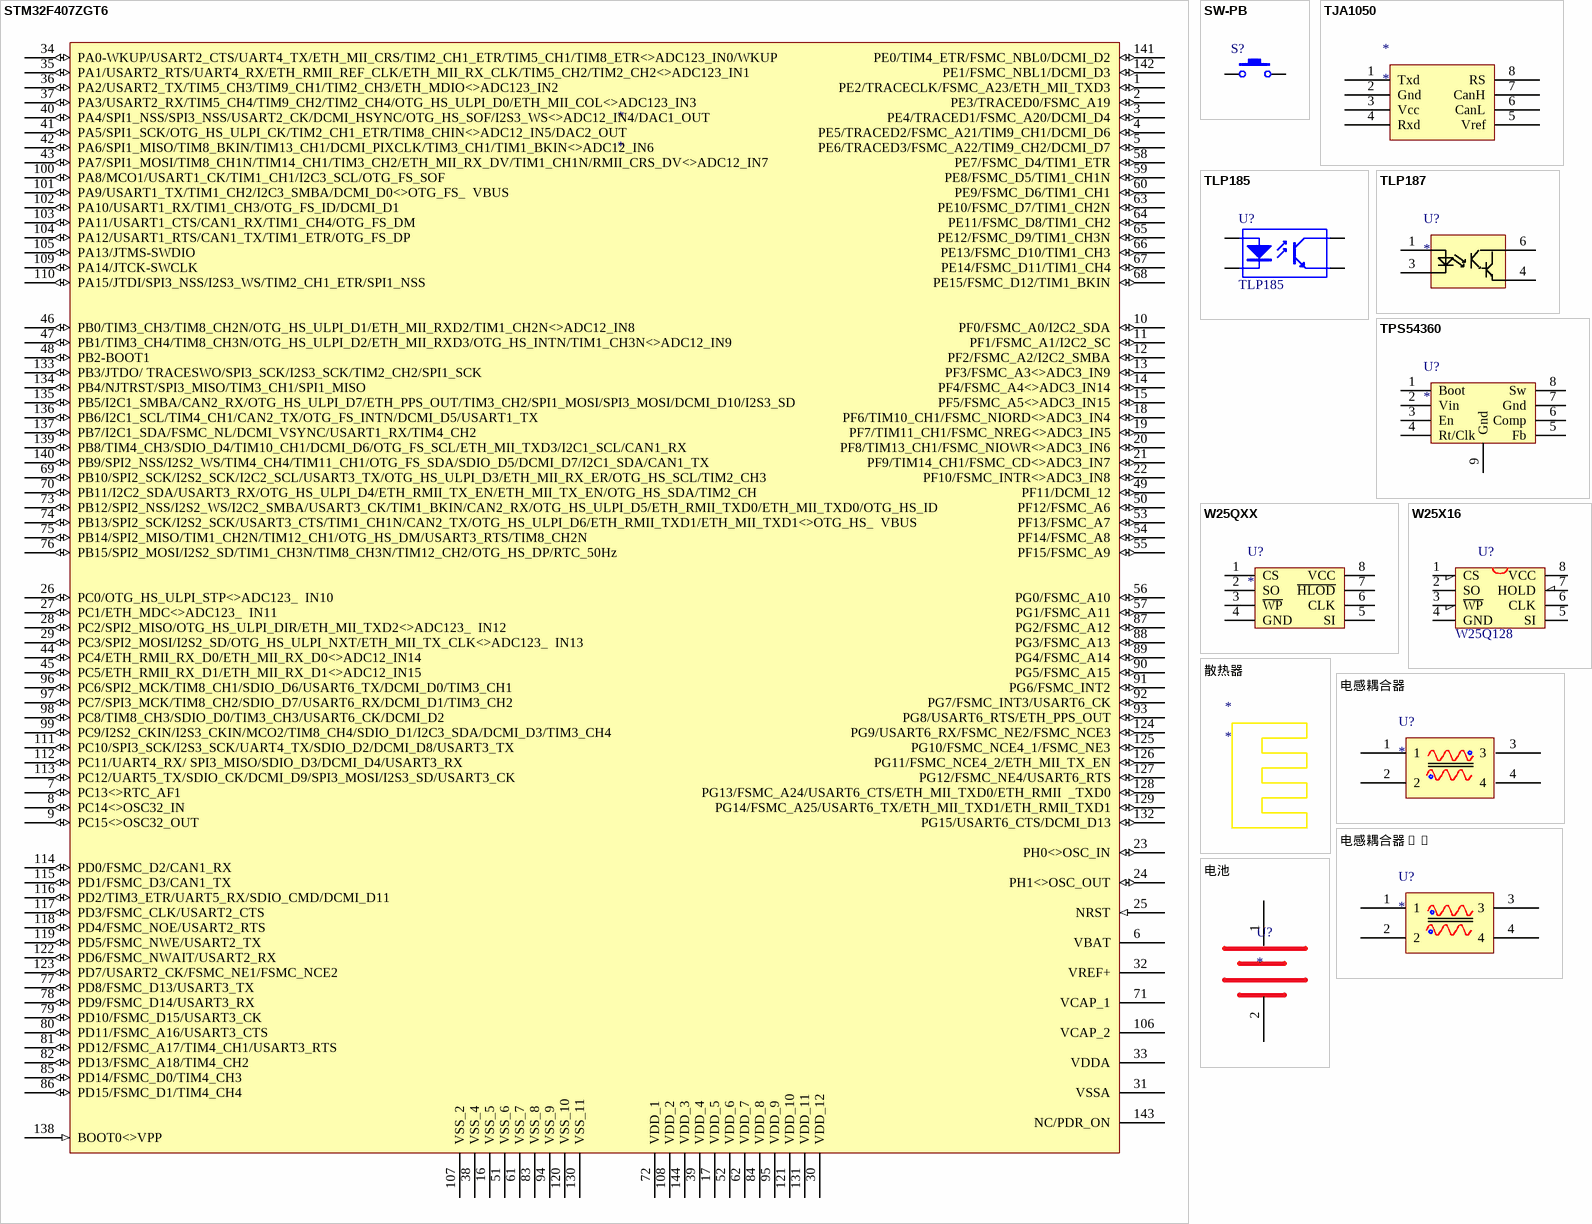
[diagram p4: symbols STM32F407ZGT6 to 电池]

## STM32F407ZGT6
designator *
pins: 1 PE2/TRACECLK/FSMC_A23/ETH_MII_TXD3 (io), 2 PE3/TRACED0/FSMC_A19 (io), 3 PE4/TRACED1/FSMC_A20/DCMI_D4 (io), 4 PE5/TRACED2/FSMC_A21/TIM9_CH1/DCMI_D6 (io), 5 PE6/TRACED3/FSMC_A22/TIM9_CH2/DCMI_D7 (io), 6 VBAT (power), 7 PC13<>RTC_AF1 (io), 8 PC14<>OSC32_IN (io), 9 PC15<>OSC32_OUT (io), 10 PF0/FSMC_A0/I2C2_SDA (io), 11 PF1/FSMC_A1/I2C2_SC (io), 12 PF2/FSMC_A2/I2C2_SMBA (io), 13 PF3/FSMC_A3<>ADC3_IN9 (io), 14 PF4/FSMC_A4<>ADC3_IN14 (io), 15 PF5/FSMC_A5<>ADC3_IN15 (io), 16 VSS_5 (power), 17 VDD_5 (power), 18 PF6/TIM10_CH1/FSMC_NIORD<>ADC3_IN4 (io), 19 PF7/TIM11_CH1/FSMC_NREG<>ADC3_IN5 (io), 20 PF8/TIM13_CH1/FSMC_NIOWR<>ADC3_IN6 (io), 21 PF9/TIM14_CH1/FSMC_CD<>ADC3_IN7 (io), 22 PF10/FSMC_INTR<>ADC3_IN8 (io), 23 PH0<>OSC_IN (io), 24 PH1<>OSC_OUT (io), 25 NRST (in), 26 PC0/OTG_HS_ULPI_STP<>ADC123_  IN10 (io), 27 PC1/ETH_MDC<>ADC123_  IN11 (io), 28 PC2/SPI2_MISO/OTG_HS_ULPI_DIR/ETH_MII_TXD2<>ADC123_  IN12 (io), 29 PC3/SPI2_MOSI/I2S2_SD/OTG_HS_ULPI_NXT/ETH_MII_TX_CLK<>ADC123_  IN13 (io), 30 VDD_12 (power), 31 VSSA (power), 32 VREF+ (power), 33 VDDA (power), 34 PA0-WKUP/USART2_CTS/UART4_TX/ETH_MII_CRS/TIM2_CH1_ETR/TIM5_CH1/TIM8_ETR<>ADC123_IN0/WKUP (io), 35 PA1/USART2_RTS/UART4_RX/ETH_RMII_REF_CLK/ETH_MII_RX_CLK/TIM5_CH2/TIM2_CH2<>ADC123_IN1 (io), 36 PA2/USART2_TX/TIM5_CH3/TIM9_CH1/TIM2_CH3/ETH_MDIO<>ADC123_IN2 (io), 37 PA3/USART2_RX/TIM5_CH4/TIM9_CH2/TIM2_CH4/OTG_HS_ULPI_D0/ETH_MII_COL<>ADC123_IN3 (io), 38 VSS_4 (power), 39 VDD_4 (power), 40 PA4/SPI1_NSS/SPI3_NSS/USART2_CK/DCMI_HSYNC/OTG_HS_SOF/I2S3_WS<>ADC12_IN4/DAC1_OUT (io), 41 PA5/SPI1_SCK/OTG_HS_ULPI_CK/TIM2_CH1_ETR/TIM8_CHIN<>ADC12_IN5/DAC2_OUT (io), 42 PA6/SPI1_MISO/TIM8_BKIN/TIM13_CH1/DCMI_PIXCLK/TIM3_CH1/TIM1_BKIN<>ADC12_IN6 (io), 43 PA7/SPI1_MOSI/TIM8_CH1N/TIM14_CH1/TIM3_CH2/ETH_MII_RX_DV/TIM1_CH1N/RMII_CRS_DV<>ADC12_IN7 (io), 44 PC4/ETH_RMII_RX_D0/ETH_MII_RX_D0<>ADC12_IN14 (io), 45 PC5/ETH_RMII_RX_D1/ETH_MII_RX_D1<>ADC12_IN15 (io), 46 PB0/TIM3_CH3/TIM8_CH2N/OTG_HS_ULPI_D1/ETH_MII_RXD2/TIM1_CH2N<>ADC12_IN8 (io), 47 PB1/TIM3_CH4/TIM8_CH3N/OTG_HS_ULPI_D2/ETH_MII_RXD3/OTG_HS_INTN/TIM1_CH3N<>ADC12_IN9 (io), 48 PB2-BOOT1 (io), 49 PF11/DCMI_12 (io), 50 PF12/FSMC_A6 (io), 51 VSS_6 (power), 52 VDD_6 (power), 53 PF13/FSMC_A7 (io), 54 PF14/FSMC_A8 (io), 55 PF15/FSMC_A9 (io), 56 PG0/FSMC_A10 (io), 57 PG1/FSMC_A11 (io), 58 PE7/FSMC_D4/TIM1_ETR (io), 59 PE8/FSMC_D5/TIM1_CH1N (io), 60 PE9/FSMC_D6/TIM1_CH1 (io), 61 VSS_7 (power), 62 VDD_7 (power), 63 PE10/FSMC_D7/TIM1_CH2N (io), 64 PE11/FSMC_D8/TIM1_CH2 (io), 65 PE12/FSMC_D9/TIM1_CH3N (io), 66 PE13/FSMC_D10/TIM1_CH3 (io), 67 PE14/FSMC_D11/TIM1_CH4 (io), 68 PE15/FSMC_D12/TIM1_BKIN (io), 69 PB10/SPI2_SCK/I2S2_SCK/I2C2_SCL/USART3_TX/OTG_HS_ULPI_D3/ETH_MII_RX_ER/OTG_HS_SCL/TIM2_CH3 (io), 70 PB11/I2C2_SDA/USART3_RX/OTG_HS_ULPI_D4/ETH_RMII_TX_EN/ETH_MII_TX_EN/OTG_HS_SDA/TIM2_CH (io), 71 VCAP_1 (power), 72 VDD_1 (power), 73 PB12/SPI2_NSS/I2S2_WS/I2C2_SMBA/USART3_CK/TIM1_BKIN/CAN2_RX/OTG_HS_ULPI_D5/ETH_RMII_TXD0/ETH_MII_TXD0/OTG_HS_ID (io), 74 PB13/SPI2_SCK/I2S2_SCK/USART3_CTS/TIM1_CH1N/CAN2_TX/OTG_HS_ULPI_D6/ETH_RMII_TXD1/ETH_MII_TXD1<>OTG_HS_  VBUS (io), 75 PB14/SPI2_MISO/TIM1_CH2N/TIM12_CH1/OTG_HS_DM/USART3_RTS/TIM8_CH2N (io), 76 PB15/SPI2_MOSI/I2S2_SD/TIM1_CH3N/TIM8_CH3N/TIM12_CH2/OTG_HS_DP/RTC_50Hz (io), 77 PD8/FSMC_D13/USART3_TX (io), 78 PD9/FSMC_D14/USART3_RX (io), 79 PD10/FSMC_D15/USART3_CK (io), 80 PD11/FSMC_A16/USART3_CTS (io), 81 PD12/FSMC_A17/TIM4_CH1/USART3_RTS (io), 82 PD13/FSMC_A18/TIM4_CH2 (io), 83 VSS_8 (power), 84 VDD_8 (power), 85 PD14/FSMC_D0/TIM4_CH3 (io), 86 PD15/FSMC_D1/TIM4_CH4 (io), 87 PG2/FSMC_A12 (io), 88 PG3/FSMC_A13 (io), 89 PG4/FSMC_A14 (io), 90 PG5/FSMC_A15 (io), 91 PG6/FSMC_INT2 (io), 92 PG7/FSMC_INT3/USART6_CK (io), 93 PG8/USART6_RTS/ETH_PPS_OUT (io), 94 VSS_9 (power), 95 VDD_9 (power), 96 PC6/SPI2_MCK/TIM8_CH1/SDIO_D6/USART6_TX/DCMI_D0/TIM3_CH1 (io), 97 PC7/SPI3_MCK/TIM8_CH2/SDIO_D7/USART6_RX/DCMI_D1/TIM3_CH2 (io), 98 PC8/TIM8_CH3/SDIO_D0/TIM3_CH3/USART6_CK/DCMI_D2 (io), 99 PC9/I2S2_CKIN/I2S3_CKIN/MCO2/TIM8_CH4/SDIO_D1/I2C3_SDA/DCMI_D3/TIM3_CH4 (io), 100 PA8/MCO1/USART1_CK/TIM1_CH1/I2C3_SCL/OTG_FS_SOF (io), 101 PA9/USART1_TX/TIM1_CH2/I2C3_SMBA/DCMI_D0<>OTG_FS_  VBUS (io), 102 PA10/USART1_RX/TIM1_CH3/OTG_FS_ID/DCMI_D1 (io), 103 PA11/USART1_CTS/CAN1_RX/TIM1_CH4/OTG_FS_DM (io), 104 PA12/USART1_RTS/CAN1_TX/TIM1_ETR/OTG_FS_DP (io), 105 PA13/JTMS-SWDIO (io), 106 VCAP_2 (power), 107 VSS_2 (power), 108 VDD_2 (power), 109 PA14/JTCK-SWCLK (io), 110 PA15/JTDI/SPI3_NSS/I2S3_WS/TIM2_CH1_ETR/SPI1_NSS (io), 111 PC10/SPI3_SCK/I2S3_SCK/UART4_TX/SDIO_D2/DCMI_D8/USART3_TX (io), 112 PC11/UART4_RX/ SPI3_MISO/SDIO_D3/DCMI_D4/USART3_RX (io), 113 PC12/UART5_TX/SDIO_CK/DCMI_D9/SPI3_MOSI/I2S3_SD/USART3_CK (io), 114 PD0/FSMC_D2/CAN1_RX (io), 115 PD1/FSMC_D3/CAN1_TX (io), 116 PD2/TIM3_ETR/UART5_RX/SDIO_CMD/DCMI_D11 (io), 117 PD3/FSMC_CLK/USART2_CTS (io), 118 PD4/FSMC_NOE/USART2_RTS (io), 119 PD5/FSMC_NWE/USART2_TX (io), 120 VSS_10 (power), 121 VDD_10 (power), 122 PD6/FSMC_NWAIT/USART2_RX (io), 123 PD7/USART2_CK/FSMC_NE1/FSMC_NCE2 (io), 124 PG9/USART6_RX/FSMC_NE2/FSMC_NCE3 (io), 125 PG10/FSMC_NCE4_1/FSMC_NE3 (io), 126 PG11/FSMC_NCE4_2/ETH_MII_TX_EN (io), 127 PG12/FSMC_NE4/USART6_RTS (io), 128 PG13/FSMC_A24/USART6_CTS/ETH_MII_TXD0/ETH_RMII  _TXD0 (io), 129 PG14/FSMC_A25/USART6_TX/ETH_MII_TXD1/ETH_RMII_TXD1 (io), 130 VSS_11 (power), 131 VDD_11 (power), 132 PG15/USART6_CTS/DCMI_D13 (io), 133 PB3/JTDO/ TRACESWO/SPI3_SCK/I2S3_SCK/TIM2_CH2/SPI1_SCK (io), 134 PB4/NJTRST/SPI3_MISO/TIM3_CH1/SPI1_MISO (io), 135 PB5/I2C1_SMBA/CAN2_RX/OTG_HS_ULPI_D7/ETH_PPS_OUT/TIM3_CH2/SPI1_MOSI/SPI3_MOSI/DCMI_D10/I2S3_SD (io), 136 PB6/I2C1_SCL/TIM4_CH1/CAN2_TX/OTG_FS_INTN/DCMI_D5/USART1_TX (io), 137 PB7/I2C1_SDA/FSMC_NL/DCMI_VSYNC/USART1_RX/TIM4_CH2 (io), 138 BOOT0<>VPP (in), 139 PB8/TIM4_CH3/SDIO_D4/TIM10_CH1/DCMI_D6/OTG_FS_SCL/ETH_MII_TXD3/I2C1_SCL/CAN1_RX (io), 140 PB9/SPI2_NSS/I2S2_WS/TIM4_CH4/TIM11_CH1/OTG_FS_SDA/SDIO_D5/DCMI_D7/I2C1_SDA/CAN1_TX (io), 141 PE0/TIM4_ETR/FSMC_NBL0/DCMI_D2 (io), 142 PE1/FSMC_NBL1/DCMI_D3 (io), 143 NC/PDR_ON (power), 144 VDD_3 (power)

## SW-PB
designator S?
Switch
footprint SPST-2 (Switch; 2 Leads)
pins: 1, 2

## TJA1050
designator *
footprint SO-8
pins: 1 Txd, 2 Gnd, 3 Vcc, 4 Rxd, 5 Vref, 6 CanL, 7 CanH, 8 RS

## TLP185
designator U?
4-Pin Phototransistor Optocoupler
footprint DIP-4 (DIP; 4 Leads; Row Spacing 7.62 mm; Pitch 2.54 mm)
footprint TLP187
footprint SO6 4PIN
pins: 1 "Anode", 3 "Cathode", 4 "Emitter", 6 "Collector"

## TLP187
designator U?
<150mA
pins: 1, 3, 4, 6

## TPS54360
designator U?
footprint SO-8
pins: 1 Boot, 2 Vin, 3 En, 4 Rt/Clk, 5 Fb, 6 Comp, 7 Gnd, 8 Sw, 9 Gnd

## W25QXX
designator U?
footprint W25QXX (SOIC, 8-Leads, Body 5.28x5.28mm, Pitch 1.27mm, IPC Medium Density)
pins: 1 CS, 2 SO, 3 ~{WP}, 4 GND, 5 SI, 6 CLK, 7 ~{HLOD}, 8 VCC

## W25X16
designator U?, comment W25Q128
W25X16;SST25VF016;MX25L1605
footprint SOIC-8 (SOIC)
pins: 1 CS, 2 SO, 3 ~{WP}, 4 GND, 5 SI, 6 CLK, 7 HOLD, 8 VCC

## 散热器
designator *

## 电感耦合器
designator U?
footprint 共模电感150uH
pins: 1, 2, 3, 4

## 电感耦合器_1
designator U?
footprint 共模电感150uH
pins: 1, 2, 3, 4

## 电池
designator U?
footprint BATM
pins: 1, 2
1 alternate drawing of the same symbol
